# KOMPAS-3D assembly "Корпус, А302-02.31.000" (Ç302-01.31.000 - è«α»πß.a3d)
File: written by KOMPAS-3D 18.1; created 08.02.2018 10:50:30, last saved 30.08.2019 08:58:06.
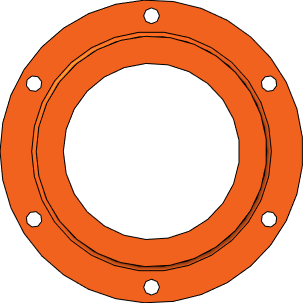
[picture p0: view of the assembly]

Document properties: Автор: Милов; Полное имя файла: D:\Мембранные насосы\Мембранный электропривод\А302-00.00.000 - ASTRA-302 (МЭ200)\3Д ПВХ\А302-01.31.000 - Корпус.a3d

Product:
- Part/product: Корпус  | designation А302-02.31.000  | pos. 0
    Масса: 0.330545
    Раздел спецификации: Сборочные единицы
    Форматы листов документа: A3
  - Component [detail]: Корпус  | designation А302-02.31.001  | pos. 1  | Масса: 0.300009; Раздел спецификации: Детали; Форматы листов документа: A4; Комментарий: С интегрированными стаканами.
- Part/product: Корпус  | designation А302-01.31.000  | pos. 0
    Масса: 0.623932
    Раздел спецификации: Сборочные единицы
    Форматы листов документа: A3
    source file: А302-01.31.000 - Корпус.cdw
  - Component [detail]: Труба ПВХ PN10 50х2,4  | pos. 4  | Масса: 0.340305; Раздел спецификации: Прочие изделия; Примечание: мм; source file: Отработка\Труба ПВХ PN10 50х2,4.m3d
  - Component [detail]: Корпус  | designation А302-01.31.001  | pos. 1  | Масса: 0.575768; Раздел спецификации: Детали; Форматы листов документа: A4; source file: А302-01.31.001 - Корпус.cdw, А302-01.31.001 - Корпус.m3d
- Part/product: Корпус  | designation А302-02.31.000-01  | pos. 0
    Масса: 0.260351
    Раздел спецификации: Сборочные единицы
    Форматы листов документа: A3
  - Component [detail]: Корпус  | designation А302-02.31.001-01  | pos. 1  | Масса: 0.260351; Раздел спецификации: Детали; Форматы листов документа: A4

Referenced files in D:\Мембранные насосы\Мембранный электропривод\А302-00.00.000 - ASTRA-302 (МЭ200)\3Д ПВХ\: А302-01.31.001 - Корпус.m3d, А302-01.31.001 - Корпус.cdw, А302-01.31.000 - Корпус.cdw
Referenced files in D:\Мембранные насосы\Мембранный электропривод\А302-00.00.000 - ASTRA-302 (МЭ200)\3Д ПВХ\Отработка\: Труба ПВХ PN10 50х2,4.m3d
